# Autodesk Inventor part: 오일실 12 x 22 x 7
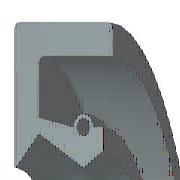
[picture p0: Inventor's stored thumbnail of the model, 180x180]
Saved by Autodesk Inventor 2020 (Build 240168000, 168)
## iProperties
Created: 2012-02
Part Number: 오일실 12 x 22 x 7
Material: 고무
Description: 오일-실
Document SubType Name: Modeling
Standard: KS B 2804
Designer: mduedu
Standards Organization: KS
Language: ko-KR
Size Designation: D - 12 22 7
Categories: <MemberInstance><Categories><Category DisplayName="샤프트 부품" InternalName="7f7aeb1f-a693-4053-b835-cee3144e0d98" Mnemonic="SHFT"><Category DisplayName="실링" Intern
Density: 0.93 g/cm^3
Mass: 1.25383 g
Surface Area: 18.4996 cm^2
Volume: 1.3482 cm^3
Appearance: 고무 - 검은색 - 버전 1.1
IsCustomPart: 1
Author: mduedu
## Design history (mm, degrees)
revolve "본체" stored, may be unused: angle "d17" = 90 deg
revolve "스프링1" stored, may be unused: angle "d18" = 90 deg
body "Solid1"
sketch "스케치1"
  geometry: L1 (0, 11)-(7, 11); L2 (7, 9.25)-(1.75, 9.25); L3 (1.75, 7.75)-(4.9, 6); L4 (4.9, 6)-(0, 6); L5 (0, 0)-(9.586, 0) reference; L6 (4.9, 6)-(6.3, 6.875); L7 (0, 18)-(0, -3) reference; L8 (-1.941, 0)-(11.507, 0) reference; L9 (4.2, 8.1)-(1.75, 8.59); L10 (1.75, 8.59)-(1.75, 9.25); L11 (0, 11)-(0, 6.088); L12 (4.9, 6)-(0, 6); L13 (1.75, 7.75)-(0.152, 6.028); L14 (7, 11)-(7, 9.25); L15 (5.6, 8.1)-(6.3, 8.1); L16 (6.3, 8.1)-(6.3, 6.875); C1 r 0.455 at (4.9, 8.1); A1 r 0.7 centre (4.9, 8.1) between (5.6, 8.1) and (4.2, 8.1); A2 r 0.088 centre (0.088, 6.088) between (0, 6.088) and (0.152, 6.028); 1 further point
  constraints: 28 end point, 5 horizontal alignment, 5 point on line, 4 point on circle, 4 vertical alignment, 3 centre point, 3 tangent, 2 collinear, 2 horizontal, 2 perpendicular, 1 coincident, 1 parallel
  dimensions: "d0" = 22 diameter of L1 L5 (= SD2); "d1" = 1.75 distance of L1.end L2.start (= SD); "d2" = 0.91 diameter of C1 (= SPDI); "d3" = 1.4 diameter of A1 (= SPDA); "d4" = 12 diameter of L3.end L5 (= NND); "d5" = 15.5 diameter of L3.start L5 (= TKDM); "d7" = 17.18 diameter of L9.end L5 (= TKDM + 0.24 x SWDT); "d8" = 1.75 distance between parallel lines of L11 L10 (= SD); "d9" = 4.9 distance from line of L11 C1.centre (= SPDST); "d10" = 16.2 diameter of C1.centre L5 (= HLDM); "d11" = 0.0875 radius of A2 (= 0.25 x LAB); "d12" = 6.3 distance between parallel lines of L11 L16 (= SDI); "d13" = 13.75 diameter of L6.end L5 (= ABDM); "d14" = 7 distance from line of L11 L1.end (= SWDT)
fillet "모깎기1" dims "d6" = 0.3 (= RR)
other parameters: "SD2" = 22 [user parameter; used in 1 equation term], "SWDT" = 7 [user parameter; used in 2 equation terms], "RR" = 0.3 [user parameter; used in 1 equation term], "SD" = 1.75 [user parameter; used in 2 equation terms], "NND" = 12 [user parameter; used in 1 equation term], "SPDA" = 1.4 [user parameter; used in 1 equation term], "SPDI" = 0.91 [user parameter; used in 1 equation term], "TKDM" = 15.5 [user parameter; used in 2 equation terms], "HLDM" = 16.2 [user parameter; used in 1 equation term], "ABDM" = 13.75 [user parameter; used in 1 equation term], "SDI" = 6.3 [user parameter; used in 1 equation term], "SPDST" = 4.9 [user parameter; used in 1 equation term], "LAB" = 0.35 [user parameter; used in 1 equation term], "d15" = 0, "d16" = 0, "d19" = 0
